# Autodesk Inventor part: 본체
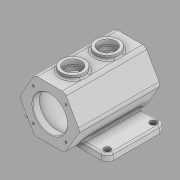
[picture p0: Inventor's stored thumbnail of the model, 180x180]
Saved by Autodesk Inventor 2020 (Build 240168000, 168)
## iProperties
Created: 2021-06
Part Number: 본체
Material: 일반
Document SubType Name: Modeling
Designer: MIRAE
Density: 1 g/cm^3
Appearance: 기본값
Author: MIRAE
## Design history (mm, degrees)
sketch "스케치1" dims "d0" = 105
  geometry: L1 (52.5, 0)-(26.25, -45.466); L2 (26.25, -45.466)-(-26.25, -45.466); L3 (-26.25, -45.466)-(-52.5, 0); L4 (-52.5, 0)-(-26.25, 45.466); L5 (-26.25, 45.466)-(26.25, 45.466); L6 (26.25, 45.466)-(52.5, 0); 3 further points
  constraints: 12 end point, 2 coincident, 1 horizontal, 1 horizontal alignment, 15 other
extrude "돌출1" new body sketch "스케치1" stored distance "d1" = 140; taper "d2" = 0 deg
node "작업 평면1"
sketch "스케치2"
  geometry: L1 (75, 45)-(-75, 45); L2 (-75, 45)-(-75, -55); L3 (-75, -55)-(75, -55); L4 (75, -55)-(75, 45); L5 (26.25, 70)-(52.5, 70) reference; L6 (52.5, -70)-(26.25, -70) reference; 3 further points
  constraints: 8 end point, 2 midpoint, 2 parallel, 1 horizontal, 1 perpendicular, 1 vertical alignment
  dimensions: "d4" = 150 distance of L2.end L3.end; "d6" = 25 distance between parallel lines of L5 L1; "d7" = 15 distance between parallel lines of L6 L3
extrude "돌출2" join sketch "스케치2" distance "d8" = 12; taper "d9" = 0 deg
fillet "모깎기1" dims "d10" = 8
fillet "모깎기2" dims "d11" = 10
fillet "모깎기3" dims "d12" = 3
fillet "모깎기4" dims "d13" = 3
sketch "스케치3"
  geometry: L1 (30, -70)-(30, -58); L2 (30, -58)-(37.5, -58); L3 (37.5, -58)-(37.5, 58); L4 (37.5, 58)-(30, 58); L5 (30, 58)-(30, 70); L6 (30, 70)-(0, 70); L7 (0, 70)-(0, -70); L8 (0, -70)-(30, -70); L9 (41.466, -70)-(4, -70) reference; 2 further points
  constraints: 16 end point, 6 perpendicular, 2 collinear, 2 point on line, 1 coincident, 1 midpoint, 1 vertical
  dimensions: "d14" = 60 diameter of L5 L7; "d15" = 75 diameter of L3 L7; "d16" = 12 distance of L1.start L1.end
revolve "회전1" sketch "스케치3" stored, may be unused: angle "d17" = 90 deg
fillet "모깎기5" dims "d18" = 5
chamfer "모따기1" distance "d19" = 1; stored, may be unused: second distance "d20" = 2, angle "d21" = 45 deg
node "작업 평면2"
sketch "스케치4"
  geometry: L1 (-21.631, 70)-(21.631, 70) reference; C1 r 20 at (0, 30); C2 r 20 at (0, -30); 1 further point
  constraints: 2 centre point, 2 vertical alignment
  dimensions: "d23" = 40 diameter of C1; "d24" = 40 distance from line of C1.centre L1; "d25" = 40 diameter of C2; "d26" = 60 distance of C2.centre C1.centre
extrude "돌출3" join sketch "스케치4" stored distance "d27" = 12; taper "d28" = 0 deg
sketch "스케치5"
  geometry: C1 r 20 at (0, 0) reference; 2 further points
  constraints: 1 coincident
hole "구멍1" sketch "스케치5" at (0, 0) diameter "d29" = 25; stored, may be unused: countersink angle "d33" = 90 deg, drill point angle "d35" = 118 deg; dims "d30" = 6, "d31" = 30, "d32" = 8, "d34" = 8
sketch "스케치6"
  geometry: C1 r 20 at (0, 0) reference; 2 further points
  constraints: 1 coincident
hole "구멍2" sketch "스케치6" at (0, 0) diameter "d36" = 25; stored, may be unused: countersink angle "d40" = 90 deg, drill point angle "d42" = 118 deg; dims "d37" = 6, "d38" = 30, "d39" = 8, "d41" = 8
chamfer "모따기2" distance "d43" = 1; stored, may be unused: second distance "d44" = 2, angle "d45" = 45 deg
sketch "스케치7"
  geometry: L1 (0, 0)-(0, 40); L2 (0, 0)-(-28.284, 28.284); A1 r 40 centre (0, 0) between (0, 40) and (-28.284, 28.284); 4 further points
  constraints: 4 end point, 2 point on circle, 1 centre point, 1 coincident, 1 vertical, 5 other
  dimensions: "d46" = 80 diameter of A1; "d47" = 45 deg angle of L1 L2; "d50" = 360 deg dimension on point (0, 0) L2.end (derived)
hole "구멍3" sketch "스케치7" at (-28.284, 28.284), (-28.284, -28.284), (28.284, -28.284), (28.284, 28.284) diameter "d52" = 3.45873; stored, may be unused: countersink angle "d56" = 90 deg, drill point angle "d58" = 118 deg; dims "d53" = 8, "d54" = 30, "d55" = 8, "d57" = 10
sketch "스케치8" dims "d59" = 80
  geometry: 6 further points
  constraints: 2 vertical alignment, 1 coincident, 7 other
  dimensions: "d62" = 360 deg dimension on point (0, 0) point (0, 40) (derived)
hole "구멍4" sketch "스케치8" at (0, 40), (-40, 0), (0, -40), (40, 0) diameter "d64" = 3.45873; stored, may be unused: countersink angle "d68" = 90 deg, drill point angle "d70" = 118 deg; dims "d65" = 8, "d66" = 30, "d67" = 8, "d69" = 10
fillet "모깎기6" dims "d71" = 3
sketch "스케치9"
  geometry: L1 (-57.998, 25.739)-(-57.998, -15.739); L2 (-57.998, -15.739)-(-64.002, -15.739); L3 (-64.002, -15.739)-(-64.002, 25.739); L4 (-64.002, 25.739)-(-57.998, 25.739); L5 (-64.002, 25.739)-(-57.998, -15.739); L6 (-75, 45)-(-75, -35) reference; L7 (-65, -45)-(-32.293, -45) reference; 2 further points
  constraints: 2 end point, 1 midpoint, 2 other
  dimensions: "d72" = 14 distance from line of point (-61, 5) L6; "d73" = 50 distance from line of point (-61, 5) L7
feature "엠보싱1" sketch "스케치9" dims "d0" = 105, "d74" = 0.5, "d75" = 0
sketch "스케치10"
  geometry: A1 r 10 centre (65, -35) between (65, -45) and (75, -35) reference; A2 r 10 centre (65, 45) between (75, 45) and (65, 55) reference; A3 r 10 centre (-65, -35) between (-75, -35) and (-65, -45) reference; A4 r 10 centre (-65, 45) between (-65, 55) and (-75, 45) reference; 5 further points
  constraints: 4 coincident
hole "구멍5" sketch "스케치10" at (65, -35), (65, 45), (-65, -35), (-65, 45) diameter "d76" = 11; stored, may be unused: countersink angle "d80" = 90 deg, drill point angle "d82" = 118 deg; dims "d77" = 8, "d78" = 30, "d79" = 8, "d81" = 10
node "솔리드1"
feature "A9D066F2-1C7D-4E18-AEED-F7BC21143FA4" dims "d76" = 11, "d77" = 8, "d78" = 30, "d79" = 8, "d80" = 90 deg, "d81" = 10, "d82" = 118 deg
other parameters: "d22" = 52.5
